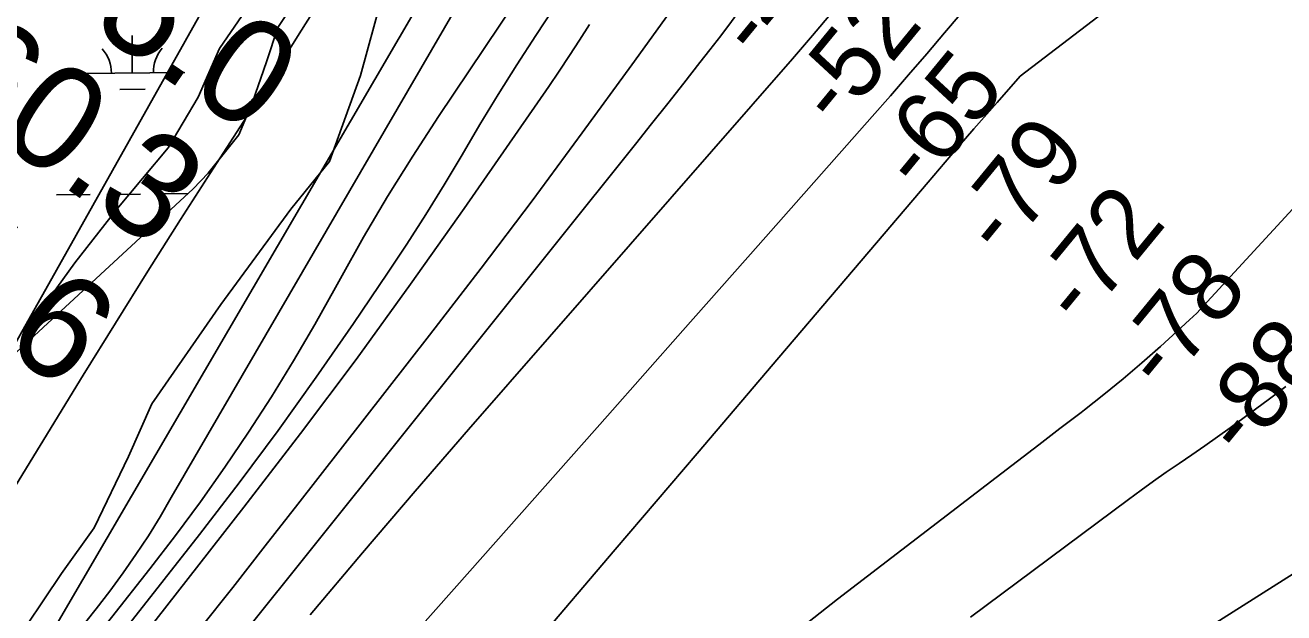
# Model space of a CAD drawing. Extents: x 3598634 to 3636690, y 517270 to 542944.
# Drawn here: x 3603624 to 3604825, y 526759 to 527320 of the extents above; entities that cross this region are included whole.
import ezdxf

# ---------------------------------------------------------------- set-up
doc = ezdxf.new("R2010")
doc.units = 0
for name, color, linetype in [('V-RIVR-EDGE', 7, 'Continuous'), ('V-RIVR-RANG', 7, 'Continuous'), ('V-SITE-VEGE', 7, 'Continuous'), ('V-SURV-IDEN', 7, 'Continuous'), ('V-TOPO-DPTH', 7, 'Continuous'), ('V-TOPO-MAJR', 7, 'Continuous'), ('V-TOPO-MINR', 7, 'Continuous'), ('V-TOPO-WATR', 7, 'Continuous'), ('V-WETL-SWMP', 7, 'Continuous')]:
    doc.layers.add(name, color=color, linetype=linetype)

msp = doc.modelspace()

# ---------------------------------------------------------------- linework, layer by layer
at = {"layer": 'V-RIVR-EDGE'}
for points in [[(3603963.4, 527345.3), (3603943.6, 527271.8), (3603922.6, 527213.7), (3603914, 527189.8), (3603877.1, 527144.5), (3603810.1, 527053.4), (3603744.3, 526958.6), (3603722.1, 526908.4), (3603689.5, 526840.5)], [(3603689.5, 526840.5), (3603658.1, 526797), (3603608.3, 526722.4), (3603536.4, 526617.2), (3603487.2, 526547.5), (3603449.7, 526513.3), (3603397.5, 526446), (3603352.6, 526379.3), (3603310.1, 526319.4), (3603276.9, 526266.8), (3603231.5, 526227.7), (3603147.4, 526150.7), (3603089, 526090.1), (3603051.5, 526024.7), (3602967.3, 525928.7), (3602940.2, 525900), (3602872.7, 525844.4), (3602823.9, 525805.3)]]:
    msp.add_lwpolyline(points, dxfattribs=at)
at = {"layer": 'V-SITE-VEGE'}
for p, q in [((3603841, 527344.7), (3603809.1, 527297.5)), ((3603809.1, 527297.5), (3603788.7, 527251.1)), ((3603788.7, 527251.1), (3603760, 527203)), ((3603760, 527203), (3603711, 527144.4)), ((3603711, 527144.4), (3603670.9, 527093.1)), ((3603670.9, 527093.1), (3603621.1, 527023.9))]:
    msp.add_line(p, q, dxfattribs=at)
at = {"layer": 'V-TOPO-DPTH'}
for points in [[(3604546.4, 528569.8), (3604348.9, 528227.9), (3604292.2, 528132.5), (3604234, 528037.9), (3604173.6, 527944.8), (3604111.7, 527852.6), (3604002.1, 527693.5), (3603993.9, 527681.7), (3603985.4, 527669.9), (3603976.9, 527658.3), (3603968.2, 527646.7), (3603583.8, 526962.7), (3603576.5, 526949.8), (3603568.8, 526937.3), (3603560.7, 526925), (3603552, 526913.2), (3603542.9, 526901.6), (3603498.3, 526847.6), (3603492.8, 526841.2), (3603487, 526834.9), (3603481, 526829), (3603474.8, 526823.2), (3603229.2, 526605.8)], [(3604709.9, 528465.1), (3604239.5, 527726.4), (3604220.9, 527697.5), (3604202.1, 527668.6), (3604183, 527640), (3604163.8, 527611.4), (3604130.6, 527562.6), (3604127.8, 527558.6), (3604125.1, 527554.6), (3604122.3, 527550.6), (3604119.6, 527546.6), (3603655.5, 526751.3)], [(3603655.5, 526751.3), (3604119.6, 527546.6), (3604122.3, 527550.6), (3604125.1, 527554.6), (3604127.8, 527558.6), (3604130.6, 527562.6), (3604163.8, 527611.4), (3604183, 527640), (3604202.1, 527668.6), (3604220.9, 527697.5), (3604239.5, 527726.4), (3604709.9, 528465.1)], [(3604798.3, 528399.2), (3604199.6, 527503.6), (3604198.1, 527501.3), (3604195.8, 527497.9), (3604193.4, 527494.5), (3604017.9, 527232.7), (3603993.3, 527194.8), (3603969.4, 527156.5), (3603946.5, 527117.6), (3603924.4, 527078.2), (3603919.6, 527069.5), (3603900, 527034.4), (3603879.7, 526999.7), (3603858.5, 526965.5), (3603836.8, 526931.6), (3603814.2, 526898.3), (3603791, 526865.4), (3603767, 526833.1), (3603742.5, 526801.2), (3603669.5, 526708.6)], [(3603669.5, 526708.6), (3603742.5, 526801.2), (3603767, 526833.1), (3603791, 526865.4), (3603814.2, 526898.3), (3603836.8, 526931.6), (3603858.5, 526965.5), (3603879.7, 526999.7), (3603900, 527034.4), (3603919.6, 527069.5), (3603924.4, 527078.2), (3603946.5, 527117.6), (3603969.4, 527156.5), (3603993.3, 527194.8), (3604017.9, 527232.7), (3604193.4, 527494.5), (3604195.8, 527497.9), (3604198.1, 527501.3), (3604199.6, 527503.6), (3604798.3, 528399.2)], [(3603790.3, 526744.2), (3603821.6, 526783.7), (3603852.7, 526823.3), (3603883.8, 526863), (3604009.4, 527024.3), (3604058.6, 527088.1), (3604107.2, 527152.3), (3604155.1, 527217), (3604202.5, 527282.1), (3604277.8, 527386.7), (3604287.2, 527399.8), (3604296.4, 527413), (3604305.6, 527426.2), (3604314.7, 527439.5), (3604422.8, 527598.8), (3604485.9, 527691.8), (3604549.1, 527784.7), (3604612.3, 527877.6), (3604675.6, 527970.4), (3604894.7, 528291.9)], [(3604894.7, 528291.9), (3604675.6, 527970.4), (3604612.3, 527877.6), (3604549.1, 527784.7), (3604485.9, 527691.8), (3604422.8, 527598.8), (3604314.7, 527439.5), (3604305.6, 527426.2), (3604296.4, 527413), (3604287.2, 527399.8), (3604277.8, 527386.7), (3604202.5, 527282.1), (3604155.1, 527217), (3604107.2, 527152.3), (3604058.6, 527088.1), (3604009.4, 527024.3), (3603883.8, 526863), (3603852.7, 526823.3), (3603821.6, 526783.7), (3603790.3, 526744.2)], [(3603751.2, 526638.6), (3604205.8, 527206.3), (3604221.3, 527225.7), (3604236.7, 527245.1), (3604252, 527264.6), (3604267.3, 527284.1), (3604276.7, 527296.2), (3604287.2, 527309.8), (3604297.5, 527323.4), (3604307.7, 527337.2), (3604317.8, 527351), (3604327.8, 527364.9), (3604337.7, 527378.9), (3604347.6, 527392.9), (3604357.4, 527406.9), (3604486, 527592.8), (3604560.3, 527699.5), (3604635.1, 527806), (3604710.6, 527912), (3604786.5, 528017.7), (3604939.1, 528228.9)], [(3604939.1, 528228.9), (3604786.5, 528017.7), (3604710.6, 527912), (3604635.1, 527806), (3604560.3, 527699.5), (3604486, 527592.8), (3604357.4, 527406.9), (3604347.6, 527392.9), (3604337.7, 527378.9), (3604327.8, 527364.9), (3604317.8, 527351), (3604307.7, 527337.2), (3604297.5, 527323.4), (3604287.2, 527309.8), (3604276.7, 527296.2), (3604267.3, 527284.1), (3604252, 527264.6), (3604236.7, 527245.1), (3604221.3, 527225.7), (3604205.8, 527206.3), (3603751.2, 526638.6)], [(3603715.7, 526711.1), (3603832.3, 526860.2), (3603886.2, 526930.4), (3603939.4, 527001.1), (3603991.3, 527072.8), (3604042.4, 527145.1), (3604123.3, 527261.5), (3604133.2, 527276.1), (3604143, 527290.8), (3604152.6, 527305.6), (3604161.9, 527320.5)], [(3604161.9, 527320.5), (3604152.6, 527305.6), (3604143, 527290.8), (3604133.2, 527276.1), (3604123.3, 527261.5), (3604042.4, 527145.1), (3603991.3, 527072.8), (3603939.4, 527001.1), (3603886.2, 526930.4), (3603832.3, 526860.2), (3603715.7, 526711.1)]]:
    msp.add_lwpolyline(points, dxfattribs=at)
at = {"layer": 'V-TOPO-MAJR'}
for points in [[(3605052.2, 528161.2), (3604745.8, 527767.5), (3604688.3, 527694.1), (3604630.3, 527621.1), (3604571.7, 527548.5), (3604512.8, 527476.2), (3604431.7, 527377.6), (3604412.9, 527355), (3604394, 527332.4), (3604374.8, 527310), (3604355.6, 527287.8), (3604046.6, 526934.1), (3603995.8, 526875.5), (3603945.4, 526816.6), (3603895.4, 526757.4)], [(3604098.7, 526331.4), (3604890.7, 526832.8)]]:
    msp.add_lwpolyline(points, dxfattribs=at)
at = {"layer": 'V-TOPO-MINR'}
for points in [[(3604546.4, 528569.8), (3604348.9, 528227.9), (3604292.2, 528132.5), (3604234, 528037.9), (3604173.6, 527944.8), (3604111.7, 527852.6), (3604002.1, 527693.5), (3603993.9, 527681.7), (3603985.4, 527669.9), (3603976.9, 527658.3), (3603968.2, 527646.7), (3603583.8, 526962.7), (3603576.5, 526949.8), (3603568.8, 526937.3), (3603560.7, 526925), (3603552, 526913.2), (3603542.9, 526901.6), (3603498.3, 526847.6), (3603492.8, 526841.2), (3603487, 526834.9), (3603481, 526829), (3603474.8, 526823.2), (3603229.2, 526605.8)], [(3604798.3, 528399.2), (3604199.6, 527503.6), (3604198.1, 527501.3), (3604195.8, 527497.9), (3604193.4, 527494.5), (3604017.9, 527232.7), (3603993.3, 527194.8), (3603969.4, 527156.5), (3603946.5, 527117.6), (3603924.4, 527078.2), (3603919.6, 527069.5), (3603900, 527034.4), (3603879.7, 526999.7), (3603858.5, 526965.5), (3603836.8, 526931.6), (3603814.2, 526898.3), (3603791, 526865.4), (3603767, 526833.1), (3603742.5, 526801.2), (3603669.5, 526708.6)], [(3604729.8, 528389.3), (3604653.7, 528271.2), (3604598.8, 528186.5), (3604543.5, 528102), (3604487.8, 528017.9), (3604431.8, 527933.9), (3604188, 527571), (3604173.2, 527549), (3604158.4, 527527), (3604143.6, 527505.1), (3604128.7, 527483.2), (3604089.8, 527425.9), (3604068.9, 527395.1), (3603762.8, 526869.5), (3603752.2, 526851), (3603741.1, 526832.8), (3603729.2, 526815), (3603717.1, 526797.4), (3603704.4, 526780.2), (3603691.4, 526763.3), (3603647.2, 526707.5)], [(3604894.7, 528291.9), (3604675.6, 527970.4), (3604612.3, 527877.6), (3604549.1, 527784.7), (3604485.9, 527691.8), (3604422.8, 527598.8), (3604314.7, 527439.5), (3604305.6, 527426.2), (3604296.4, 527413), (3604287.2, 527399.8), (3604277.8, 527386.7), (3604202.5, 527282.1), (3604155.1, 527217), (3604107.2, 527152.3), (3604058.6, 527088.1), (3604009.4, 527024.3), (3603883.8, 526863), (3603852.7, 526823.3), (3603821.6, 526783.7), (3603790.3, 526744.2)], [(3604939.1, 528228.9), (3604786.5, 528017.7), (3604710.6, 527912), (3604635.1, 527806), (3604560.3, 527699.5), (3604486, 527592.8), (3604357.4, 527406.9), (3604347.6, 527392.9), (3604337.7, 527378.9), (3604327.8, 527364.9), (3604317.8, 527351), (3604307.7, 527337.2), (3604297.5, 527323.4), (3604287.2, 527309.8), (3604276.7, 527296.2), (3604267.3, 527284.1), (3604252, 527264.6), (3604236.7, 527245.1), (3604221.3, 527225.7), (3604205.8, 527206.3), (3603751.2, 526638.6)], [(3605219.6, 527765.1), (3604573.1, 527271.3), (3604550.9, 527246.2), (3604528.8, 527221), (3604506.9, 527195.6), (3604485.1, 527170.2), (3604342.7, 527002.8), (3604264.7, 526911.2), (3604186.6, 526819.7), (3604108.5, 526728.2)], [(3604830, 527703.8), (3604769.9, 527631.5), (3604709.6, 527559.3), (3604649.1, 527487.4), (3604588.4, 527415.6), (3604500.9, 527312.6), (3604483.8, 527292.5), (3604466.5, 527272.5), (3604449.2, 527252.6), (3604431.7, 527232.7), (3604323, 527109.8), (3604251.2, 527028.6), (3604179.3, 526947.4), (3604107.4, 526866.2), (3604035.4, 526785.1), (3603829.8, 526553.3)], [(3604182.9, 527419.9), (3604110.7, 527310), (3604092.6, 527281.9), (3604074.8, 527253.6), (3604057.4, 527225.1), (3604040.4, 527196.3), (3604023.3, 527167.6), (3604005.8, 527139.2), (3603987.7, 527111.1), (3603969.3, 527083.2), (3603936.8, 527035.3), (3603901.3, 526984.1), (3603865.1, 526933.3), (3603827.8, 526883.4), (3603789.8, 526834), (3603692.3, 526709.8)], [(3603903.6, 527341.2), (3603885.1, 527311.5), (3603866.4, 527281.9), (3603847.7, 527252.3), (3603828.7, 527222.9), (3603803.3, 527183.6), (3603771.8, 527134.5), (3603740.5, 527085.2), (3603709.6, 527035.7), (3603678.9, 526986), (3603559.1, 526790.6)], [(3604161.9, 527320.5), (3604152.6, 527305.6), (3604143, 527290.8), (3604133.2, 527276.1), (3604123.3, 527261.5), (3604042.4, 527145.1), (3603991.3, 527072.8), (3603939.4, 527001.1), (3603886.2, 526930.4), (3603832.3, 526860.2), (3603715.7, 526711.1)], [(3604970.3, 527293.5), (3604747.9, 527052.1), (3604744.7, 527048.7), (3604741.4, 527045.3), (3604738.1, 527042.1), (3604734.6, 527038.9), (3604706.7, 527013.4), (3604689, 526997.7), (3604671.1, 526982.4), (3604652.8, 526967.5), (3604634.2, 526952.9), (3604631.2, 526950.6), (3604610.9, 526935.1), (3604590.7, 526919.6), (3604570.4, 526904.1), (3604550.2, 526888.6), (3604398.5, 526772.4), (3604320.5, 526710.8)], [(3604525.5, 526755.1), (3604676.3, 526867.6), (3604688.3, 526876.4), (3604700.3, 526885), (3604712.4, 526893.5), (3604724.7, 526901.9), (3604736.9, 526910.2), (3604749.1, 526918.6), (3604761.2, 526927.2), (3604773.2, 526935.9), (3604810.7, 526963.4), (3604818.6, 526969.3), (3604826.3, 526975.3)]]:
    msp.add_lwpolyline(points, dxfattribs=at)
at = {"layer": 'V-TOPO-WATR'}
msp.add_lwpolyline([(3604709.9, 528465.1), (3604239.5, 527726.4), (3604220.9, 527697.5), (3604202.1, 527668.6), (3604183, 527640), (3604163.8, 527611.4), (3604130.6, 527562.6), (3604127.8, 527558.6), (3604125.1, 527554.6), (3604122.3, 527550.6), (3604119.6, 527546.6), (3603655.5, 526751.3)], dxfattribs=at)
at = {"layer": 'V-WETL-SWMP'}
for p, q in [((3603725.8, 527274.1), (3603725.5, 527310.1)), ((3603675.8, 527273.7), (3603775.8, 527274.6)), ((3603714, 527258.6), (3603738, 527258.8)), ((3603653.5, 527158), (3603685.5, 527158.3)), ((3603701.5, 527158.5), (3603733.5, 527158.8)), ((3603749.5, 527158.9), (3603779, 527159.2))]:
    msp.add_line(p, q, dxfattribs=at)
msp.add_lwpolyline([(3603882.7, 527345.2), (3603864.7, 527317.7), (3603853.7, 527284.8), (3603840.5, 527246.3), (3603827.3, 527215.3), (3603798.3, 527178.6), (3603783.9, 527163.7), (3603514, 526914.9)], dxfattribs=at)
for centre, start, end in [((3603670.6, 527274.1), 359.7615, 41.3052), ((3603781.1, 527275.1), 139.7615, 181.3052)]:
    msp.add_arc(centre, 35.2, start, end, dxfattribs=at)

# ---------------------------------------------------------------- texts
at = {"layer": 'V-RIVR-RANG'}
for s, p in [('-43', (3604323, 527285.4)), ('-52', (3604399.1, 527220.5)), ('-65', (3604478.2, 527159.2)), ('-79', (3604556.1, 527096.6)), ('-72', (3604631.4, 527030.6)), ('-78', (3604709.8, 526968.6)), ('-88', (3604786.6, 526904.5))]:
    msp.add_text(s, height=67, rotation=50.5771, dxfattribs=at).set_placement(p)
at = {"layer": 'V-SURV-IDEN'}
for s, rotation, p in [('5757+85.0', 325.8769, (3603311.9, 527570.4)), ('5756+60.3', 324.8193, (3603226.8, 527471.3)), ('5754+64.6', 322.9883, (3603151.4, 527352.8))]:
    msp.add_text(s, height=100, rotation=rotation, dxfattribs=at).set_placement(p)

doc.saveas('drawing.dxf')
